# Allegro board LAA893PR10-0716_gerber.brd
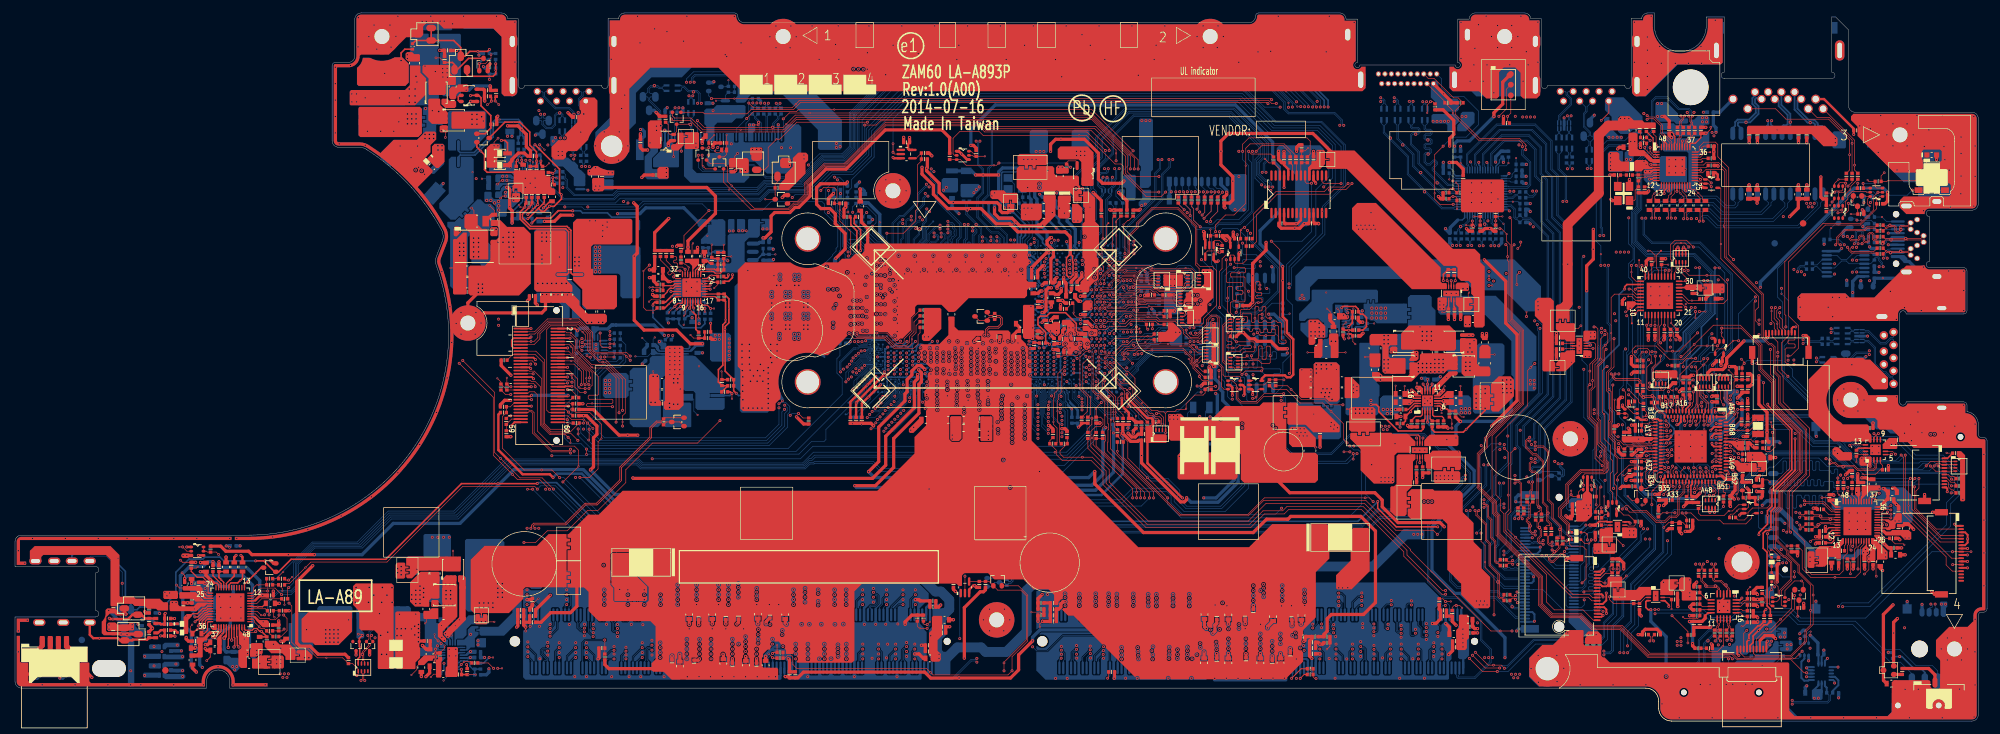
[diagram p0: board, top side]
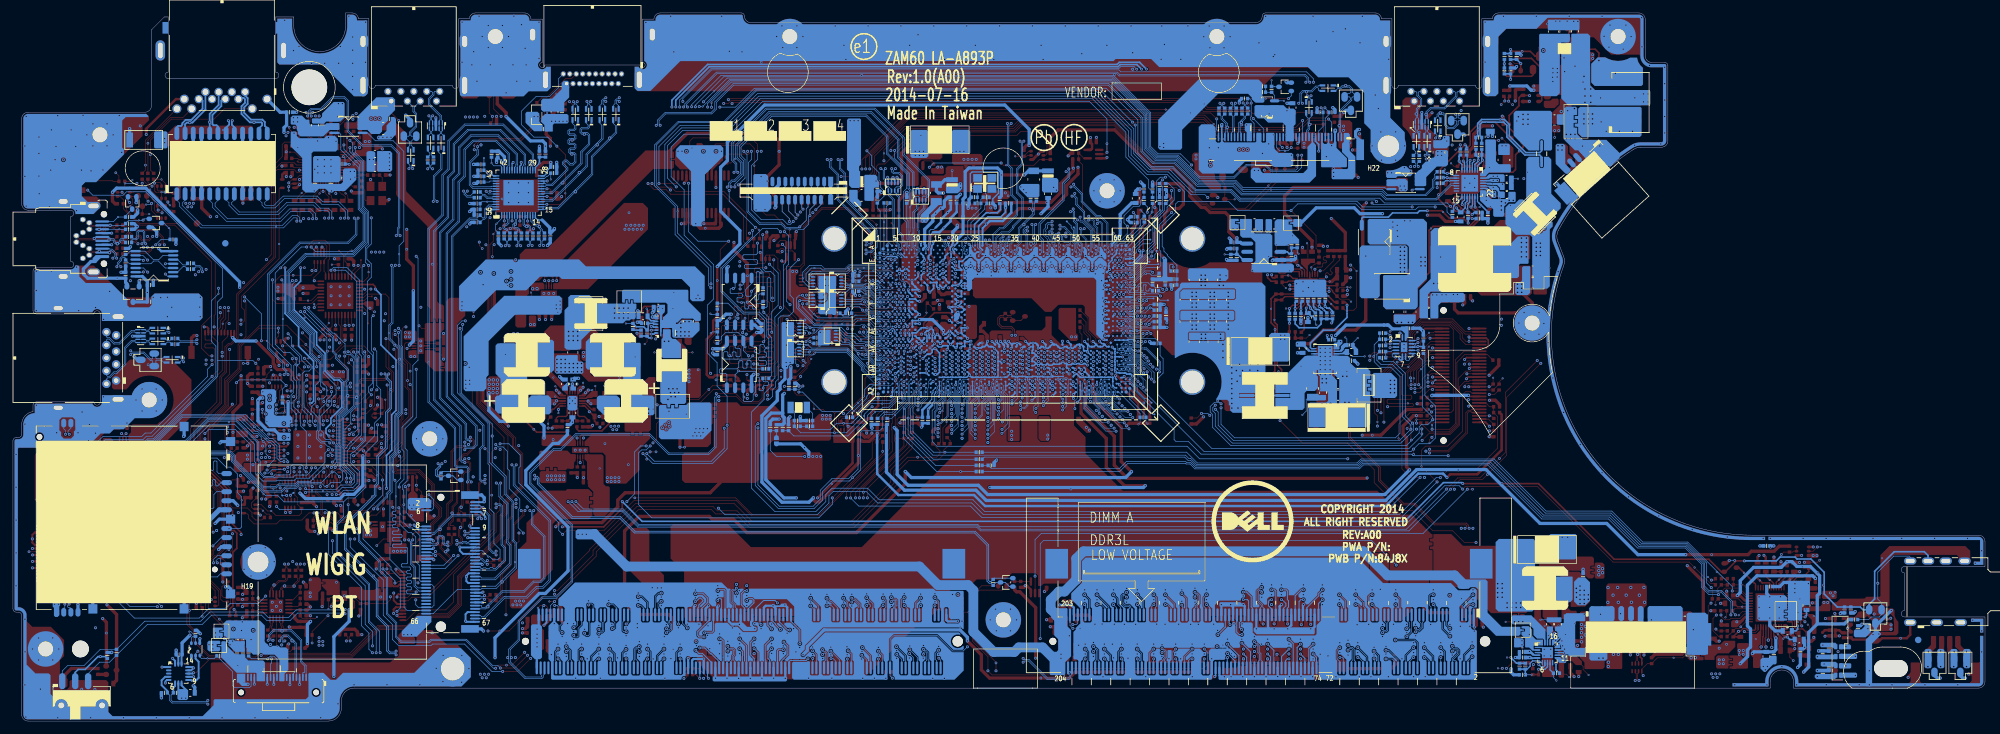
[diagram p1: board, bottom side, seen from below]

Outline 304.75 x 109.5 mm; copper layers: TOP, VCC, IN1, IN2, GND, BOTTOM. Coordinates in mm from the lower left corner of the outline.
Outline path: 0,27.75 arc(0.29,28.46) 1,28.75 36,28.75 arc(61.42,42.01) 65.1,70.44 arc(64.98,71.14) 65.11,71.85 66.03,74.22 arc(66.16,75.07) 65.92,75.89 arc(60.9,82.9) 54.28,88.42 arc(53.76,88.65) 53.2,88.73 50,88.73 arc(49.29,89.03) 49,89.73 49,101.35 arc(49.15,101.7) 49.5,101.85 51.5,101.85 arc(52.21,102.14) 52.5,102.85 52.5,108.5 arc(52.79,109.21) 53.5,109.5 75.15,109.5 arc(75.83,109.24) 76.15,108.6 77.75,108.6 77.75,98.3 arc(78.25,97.8) 78.75,98.3 90.65,98.3 arc(91.15,97.8) 91.65,98.3 91.65,108.6 93.25,108.6 arc(93.57,109.24) 94.24,109.5 111.2,109.5 arc(111.55,109.35) 111.7,109 arc(111.99,108.29) 112.7,108 190.7,108 arc(191.41,108.29) 191.7,109 arc(191.85,109.35) 192.2,109.5 204.7,109.5 arc(205.39,109.22) 205.7,108.55 207.45,108.55 207.45,101.85 arc(207.17,101.17) 207.85,101.45 222.55,101.45 arc(223.23,101.17) 222.95,101.85 222.95,108.55 224.7,108.55 arc(225.01,109.22) 225.7,109.5 233.25,109.5 arc(233.93,109.24) 234.25,108.6 235.85,108.6 235.85,98.3 arc(236.35,97.8) 236.85,98.3 248.75,98.3 arc(249.25,97.8) 249.75,98.3 249.75,108.6 251.35,108.6 arc(251.67,109.24) 252.34,109.5 253.35,109.5 253.35,107.5 arc(257.35,103.5) 261.35,107.5 261.35,108.88 264.15,108.88 264.15,100.35 arc(263.65,99.87) 264.1,99.35 arc(264.13,99.35) 264.15,99.35 280.75,99.35 arc(280.77,99.35) 280.8,99.35 arc(281.25,99.87) 280.75,100.35 280.75,108.88 281.35,108.88 283.35,106.88 283.35,95.15 arc(283.64,94.44) 284.35,94.15 302.4,94.15 arc(303.11,93.86) 303.4,93.15 303.4,80 arc(303.11,79.29) 302.4,79 295.85,79 arc(295.35,78.5) 295.85,78 295.85,71.1 arc(295.35,70.6) 295.85,70.1 301.15,70.1 arc(301.5,69.95) 301.65,69.6 301.65,63.45 arc(301.5,63.1) 301.15,62.95 292.25,62.95 arc(291.75,63.45) 291.25,62.95 291.25,49.35 arc(291.75,48.85) 292.25,49.35 301.15,49.35 arc(301.49,49.21) 301.65,48.88 301.65,47.85 arc(302.9,47.19) 303.4,45.87 303.4,44.34 arc(303.55,43.99) 303.9,43.84 304.25,43.84 arc(304.6,43.69) 304.75,43.34 304.75,17.35 arc(304.6,16.99) 304.25,16.85 303.9,16.85 arc(303.55,16.7) 303.4,16.35 303.4,1 arc(303.11,0.29) 302.4,0 256,0 arc(254.59,0.59) 254,2 254,3.1 arc(253.41,4.51) 252,5.1 33.2,5.1 33.2,6.1 arc(31.4,7.9) 29.6,6.1 29.6,5.1 1,5.1 arc(0.29,5.39) 0,6.1 0,16.1 12.45,16.1 arc(12.95,16.6) 12.45,17.1 12.45,22.9 arc(12.95,23.4) 12.45,23.9 0,23.9 0,27.75

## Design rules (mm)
net group CLK_PCIE_LAN: nets CLK_PCIE_LAN CLK_PCIE_LAN#
net group CLK_PCIE_MMI: nets CLK_PCIE_MMI CLK_PCIE_MMI#
net group CLK_PCIE_WIGIG: nets CLK_PCIE_WIGIG CLK_PCIE_WIGIG#
net group CLK_PCIE_WLAN: nets CLK_PCIE_WLAN CLK_PCIE_WLAN#
net group CPU_DPB_CTRLCLK: nets CPU_DPB_CTRLCLK CPU_DPB_CTRLDAT
net group CPU_DPC_CTRLCLK: nets CPU_DPC_CTRLCLK CPU_DPC_CTRLDAT
net group DDR_A_DQS0: nets DDR_A_DQS0 DDR_A_DQS#0
net group DDR_A_DQS1: nets DDR_A_DQS1 DDR_A_DQS#1
net group DDR_A_DQS2: nets DDR_A_DQS2 DDR_A_DQS#2
net group DDR_A_DQS3: nets DDR_A_DQS3 DDR_A_DQS#3
net group DDR_A_DQS4: nets DDR_A_DQS4 DDR_A_DQS#4
net group DDR_A_DQS5: nets DDR_A_DQS5 DDR_A_DQS#5
net group DDR_A_DQS6: nets DDR_A_DQS6 DDR_A_DQS#6
net group DDR_A_DQS7: nets DDR_A_DQS7 DDR_A_DQS#7
net group DDR_B_DQS0: nets DDR_B_DQS0 DDR_B_DQS#0
net group DDR_B_DQS1: nets DDR_B_DQS1 DDR_B_DQS#1
net group DDR_B_DQS2: nets DDR_B_DQS2 DDR_B_DQS#2
net group DDR_B_DQS3: nets DDR_B_DQS3 DDR_B_DQS#3
net group DDR_B_DQS4: nets DDR_B_DQS4 DDR_B_DQS#4
net group DDR_B_DQS5: nets DDR_B_DQS5 DDR_B_DQS#5
net group DDR_B_DQS6: nets DDR_B_DQS6 DDR_B_DQS#6
net group DDR_B_DQS7: nets DDR_B_DQS7 DDR_B_DQS#7
net group DIFFPAIR0: nets MCP_TESTLOW1 MCP_TESTLOW2
net group DIFFPAIR1: nets HDMI_CLK_AUX HDMI_DAT_AUX#
net group DIFFPAIR3: nets DMIC1 DMIC_CLK1
net group DIFFPAIR4: nets DMIC0 DMIC_CLK0
net group DIFFPAIR5: nets BC_CLK_ECE1117 BC_DAT_ECE1117
net group DIFFPAIR6: nets REM_DIODE4_N_R REM_DIODE4_P_R
net group EDP_CPU_AUX_C: nets EDP_CPU_AUX#_C EDP_CPU_AUX_C
net group M_CLK_DDR0: nets M_CLK_DDR0 M_CLK_DDR#0
net group M_CLK_DDR1: nets M_CLK_DDR1 M_CLK_DDR#1
net group M_CLK_DDR2: nets M_CLK_DDR2 M_CLK_DDR#2
net group M_CLK_DDR3: nets M_CLK_DDR3 M_CLK_DDR#3
net group MDP_AUX_C: nets MDP_AUX#_C MDP_AUX_C
net group PBAT_SMBCLK_C: nets PBAT_SMBCLK_C PBAT_SMBDAT_C
net group PS_USBP1_D: nets PS_USBP1_D+ PS_USBP1_D-
net group SATA_PRX_DTX_1: nets SATA_PRX_DTX_N1 SATA_PRX_DTX_P1
net group SATA_PRX_DTX_1_C: nets SATA_PRX_DTX_N1_C SATA_PRX_DTX_P1_C
net group SATA_PRX_DTX_1_RP: nets SATA_PRX_DTX_N1_RP SATA_PRX_DTX_P1_RP
net group SATA_PRX_DTX_1_RP_C: nets SATA_PRX_DTX_N1_RP_C SATA_PRX_DTX_P1_RP_C
net group SATA_PTX_DRX_1: nets SATA_PTX_DRX_N1 SATA_PTX_DRX_P1
net group SATA_PTX_DRX_1_C: nets SATA_PTX_DRX_N1_C SATA_PTX_DRX_P1_C
net group SATA_PTX_DRX_1_RP: nets SATA_PTX_DRX_N1_RP SATA_PTX_DRX_P1_RP
net group SATA_PTX_DRX_1_RP_C: nets SATA_PTX_DRX_N1_RP_C SATA_PTX_DRX_P1_RP_C
net group SENSE: nets VCCSENSE VSSSENSE
net group SINGLE-CLK: nets CLK_PCI_LPDEBUG CLK_PCI_MEC
net group SW_MDP_AUX: nets SW_MDP_AUX#_C SW_MDP_AUX_C
net group TMDS_CON_CLK: nets TMDS_CON_CLK TMDS_CON_CLK#
net group USB2.0: nets USBP4+ USBP4-
net group USB3RN1_D: nets USB3RN1_D- USB3RP1_D+
net group USB3RN2_D: nets USB3RN2_D- USB3RP2_D+
net group USB3RP4_D: nets USB3RN4_D- USB3RP4_D+
net group USB3T1: nets USB3TN1 USB3TP1
net group USB3T1_C: nets USB3TN1_C USB3TP1_C
net group USB3T2: nets USB3TN2 USB3TP2
net group USB3T2_C: nets USB3TN2_C USB3TP2_C
net group USB3T4: nets USB3TN4 USB3TP4
net group USB3T4_C: nets USB3TN4_C USB3TP4_C
net group USB3TN1_D: nets USB3TN1_D- USB3TP1_D+
net group USB3TN2_D: nets USB3TN2_D- USB3TP2_D+
net group USB3TP4_D: nets USB3TN4_D- USB3TP4_D+
net group USBP0: nets USBP0+ USBP0-
net group USBP0_D: nets USBP0_D+ USBP0_D-
net group USBP1: nets USBP1+ USBP1-
net group USBP1_R_D: nets USBP1_R_D+ USBP1_R_D-
net group USBP2: nets USBP2+ USBP2-
net group USBP3: nets USBP3+ USBP3-
net group USBP3_D: nets USBP3_D+ USBP3_D-
net group USBP4_D: nets USBP4_D+ USBP4_D-
net group USBP5: nets USBP5+ USBP5-
net group USBP5_D: nets USBP5_D+ USBP5_D-
net group WIGIG_AUX: nets WIGIG_AUX WIGIG_AUX#
net group WIGIG_AUX_C: nets WIGIG_AUX#_C WIGIG_AUX_C
net group 10: nets +PCH_ASATA3PLL +PCH_AUSB3PLL AUD_HP_OUT_L AUD_HP_OUT_L1 AUD_HP_OUT_R AUD_HP_OUT_R1 AUD_OUT_L AUD_OUT_R CFG_RCOMP PCH_PCIE_RCOMP PROC_OPI_RCOMP SATA_COMP SM_RCOMP0 SM_RCOMP1 SM_RCOMP2 TDI_IREF
net group 12/15: nets H_CATERR# H_PROCHOT# H_PROCHOT#_R H_THERMTRIP# H_THERMTRIP#_R PCH_PLTRST# PCH_PLTRST#_EC PLTRST_LAN# PLTRST_MMI# THERMATRIP2# THERMATRIP3# XDP_OBS0_R XDP_OBS1_R XDP_OBS2_R XDP_OBS3_R XDP_OBS4_R XDP_OBS5_R XDP_OBS6_R XDP_OBS7_R XDP_RST#_R
net group 15: nets CHARGER_SMBCLK CLK_TP_SIO DDR_XDP_WAN_SMBCLK GPU_SMBCLK MEM_SMBCLK PBAT_SMBCLK PCH_SPI_CLK SML0_SMBCLK SML1_SMBCLK SPI_CLK32 SPI_CLK64 SPI_PCH_CLK SYS_PWROK USH_SMBCLK
net group 20: nets +SM_VREF_CA +SM_VREF_DQ0 +SM_VREF_DQ1 DDR3_DRAMRST# EDP_COMP
net group ASYNC: nets H_CPUPWRGD PCH_JTAG_TCK PCH_JTAG_TDI PCH_JTAG_TDO PCH_JTAG_TMS
net group BUS_CL: nets PCH_CL_CLK1 PCH_CL_DATA1 PCH_CL_RST1#
net group BUS_RTC: nets PCH_RTCRST# PCH_RTCX1 PCH_RTCX1_R PCH_RTCX2 SRTCRST#
net group DDI1: nets CPU_DPB_AUX CPU_DPB_AUX# DDI1_LANE_N0 DDI1_LANE_N1 DDI1_LANE_N2 DDI1_LANE_N3 DDI1_LANE_P0 DDI1_LANE_P1 DDI1_LANE_P2 DDI1_LANE_P3 MDP_LANE_N0_C MDP_LANE_N1_C MDP_LANE_N2_C MDP_LANE_N3_C MDP_LANE_P0_C MDP_LANE_P1_C MDP_LANE_P2_C MDP_LANE_P3_C
net group DDI2: nets CPU_DPC_AUX CPU_DPC_AUX# CPU_DPC_AUX#_C CPU_DPC_AUX_C DDI2_LANE_N0 DDI2_LANE_N0_C DDI2_LANE_N1 DDI2_LANE_N1_C DDI2_LANE_N2 DDI2_LANE_N2_C DDI2_LANE_N3 DDI2_LANE_N3_C DDI2_LANE_P0 DDI2_LANE_P0_C DDI2_LANE_P1 DDI2_LANE_P1_C DDI2_LANE_P2 DDI2_LANE_P2_C DDI2_LANE_P3 DDI2_LANE_P3_C
net group DDRA_CMD: nets DDR_A_BS0 DDR_A_BS1 DDR_A_BS2 DDR_A_CAS# DDR_A_MA0 DDR_A_MA1 DDR_A_MA2 DDR_A_MA3 DDR_A_MA4 DDR_A_MA5 DDR_A_MA6 DDR_A_MA7 DDR_A_MA8 DDR_A_MA9 DDR_A_MA10 DDR_A_MA11 DDR_A_MA12 DDR_A_MA13 DDR_A_MA14 DDR_A_MA15 DDR_A_RAS# DDR_A_WE#
net group DDRA_CTL: nets DDR_CKE0_DIMMA DDR_CKE1_DIMMA DDR_CS0_DIMMA# DDR_CS1_DIMMA# M_ODT0 M_ODT1
net group DDRB_CMD: nets DDR_B_BS0 DDR_B_BS1 DDR_B_BS2 DDR_B_CAS# DDR_B_MA0 DDR_B_MA1 DDR_B_MA2 DDR_B_MA3 DDR_B_MA4 DDR_B_MA5 DDR_B_MA6 DDR_B_MA7 DDR_B_MA8 DDR_B_MA9 DDR_B_MA10 DDR_B_MA11 DDR_B_MA12 DDR_B_MA13 DDR_B_MA14 DDR_B_MA15 DDR_B_RAS# DDR_B_WE#
net group DDRB_CTL: nets DDR_CKE2_DIMMB DDR_CKE3_DIMMB DDR_CS2_DIMMB# DDR_CS3_DIMMB# M_ODT2 M_ODT3
net group EDP: nets EDP_CPU_AUX EDP_CPU_AUX# EDP_CPU_LANE_N0 EDP_CPU_LANE_N0_C EDP_CPU_LANE_N1 EDP_CPU_LANE_N1_C EDP_CPU_LANE_P0 EDP_CPU_LANE_P0_C EDP_CPU_LANE_P1 EDP_CPU_LANE_P1_C
net group HDA: nets ME_FWP PCH_AZ_BITCLK PCH_AZ_CODEC_BITCLK PCH_AZ_CODEC_RST# PCH_AZ_CODEC_SDIN0 PCH_AZ_CODEC_SDOUT PCH_AZ_CODEC_SYNC PCH_AZ_RST# PCH_AZ_SDIN0_R PCH_AZ_SDOUT PCH_AZ_SYNC
net group HDMI: nets HDMI_LANE_N0 HDMI_LANE_N1 HDMI_LANE_N2 HDMI_LANE_N3 HDMI_LANE_P0 HDMI_LANE_P1 HDMI_LANE_P2 HDMI_LANE_P3 TMDS_CON_N0 TMDS_CON_N1 TMDS_CON_N2 TMDS_CON_P0 TMDS_CON_P1 TMDS_CON_P2
net group LAN: nets LAN_TX0+ LAN_TX0+L LAN_TX0- LAN_TX0-L LAN_TX1+ LAN_TX1+L LAN_TX1- LAN_TX1-L LAN_TX2+ LAN_TX2+L LAN_TX2- LAN_TX2-L LAN_TX3+ LAN_TX3+L LAN_TX3- LAN_TX3-L
net group MEM_SMB: nets MEM_SMBDATA
net group PCIE: nets PCIE_PRX_GLANTX_N3 PCIE_PRX_GLANTX_N3_C PCIE_PRX_GLANTX_P3 PCIE_PRX_GLANTX_P3_C PCIE_PRX_MMITX_N1 PCIE_PRX_MMITX_N1_C PCIE_PRX_MMITX_P1 PCIE_PRX_MMITX_P1_C PCIE_PRX_WIGIGTX_N5 PCIE_PRX_WIGIGTX_P5 PCIE_PRX_WLANTX_N4 PCIE_PRX_WLANTX_P4 PCIE_PTX_GLANRX_N3 PCIE_PTX_GLANRX_N3_C PCIE_PTX_GLANRX_P3 PCIE_PTX_GLANRX_P3_C PCIE_PTX_MMIRX_N1 PCIE_PTX_MMIRX_N1_C PCIE_PTX_MMIRX_P1 PCIE_PTX_MMIRX_P1_C PCIE_PTX_WIGIGRX_N5 PCIE_PTX_WIGIGRX_N5_C PCIE_PTX_WIGIGRX_P5 PCIE_PTX_WIGIGRX_P5_C PCIE_PTX_WLANRX_N4 PCIE_PTX_WLANRX_N4_C PCIE_PTX_WLANRX_P4 PCIE_PTX_WLANRX_P4_C
net group R_DQA0: nets DDR_A_D0 DDR_A_D1 DDR_A_D2 DDR_A_D3 DDR_A_D4 DDR_A_D5 DDR_A_D6 DDR_A_D7
net group R_DQA1: nets DDR_A_D8 DDR_A_D9 DDR_A_D10 DDR_A_D11 DDR_A_D12 DDR_A_D13 DDR_A_D14 DDR_A_D15
net group R_DQA2: nets DDR_A_D16 DDR_A_D17 DDR_A_D18 DDR_A_D19 DDR_A_D20 DDR_A_D21 DDR_A_D22 DDR_A_D23
net group R_DQA3: nets DDR_A_D24 DDR_A_D25 DDR_A_D26 DDR_A_D27 DDR_A_D28 DDR_A_D29 DDR_A_D30 DDR_A_D31
net group R_DQA4: nets DDR_A_D32 DDR_A_D33 DDR_A_D34 DDR_A_D35 DDR_A_D36 DDR_A_D37 DDR_A_D38 DDR_A_D39
net group R_DQA5: nets DDR_A_D40 DDR_A_D41 DDR_A_D42 DDR_A_D43 DDR_A_D44 DDR_A_D45 DDR_A_D46 DDR_A_D47
net group R_DQA6: nets DDR_A_D48 DDR_A_D49 DDR_A_D50 DDR_A_D51 DDR_A_D52 DDR_A_D53 DDR_A_D54 DDR_A_D55
net group R_DQA7: nets DDR_A_D56 DDR_A_D57 DDR_A_D58 DDR_A_D59 DDR_A_D60 DDR_A_D61 DDR_A_D62 DDR_A_D63
net group R_DQB0: nets DDR_B_D0 DDR_B_D1 DDR_B_D2 DDR_B_D3 DDR_B_D4 DDR_B_D5 DDR_B_D6 DDR_B_D7
net group R_DQB1: nets DDR_B_D8 DDR_B_D9 DDR_B_D10 DDR_B_D11 DDR_B_D12 DDR_B_D13 DDR_B_D14 DDR_B_D15
net group R_DQB2: nets DDR_B_D16 DDR_B_D17 DDR_B_D18 DDR_B_D19 DDR_B_D20 DDR_B_D21 DDR_B_D22 DDR_B_D23
net group R_DQB3: nets DDR_B_D24 DDR_B_D25 DDR_B_D26 DDR_B_D27 DDR_B_D28 DDR_B_D29 DDR_B_D30 DDR_B_D31
net group R_DQB4: nets DDR_B_D32 DDR_B_D33 DDR_B_D34 DDR_B_D35 DDR_B_D36 DDR_B_D37 DDR_B_D38 DDR_B_D39
net group R_DQB5: nets DDR_B_D40 DDR_B_D41 DDR_B_D42 DDR_B_D43 DDR_B_D44 DDR_B_D45 DDR_B_D46 DDR_B_D47
net group R_DQB6: nets DDR_B_D48 DDR_B_D49 DDR_B_D50 DDR_B_D51 DDR_B_D52 DDR_B_D53 DDR_B_D54 DDR_B_D55
net group R_DQB7: nets DDR_B_D56 DDR_B_D57 DDR_B_D58 DDR_B_D59 DDR_B_D60 DDR_B_D61 DDR_B_D62 DDR_B_D63
net group RJ45: nets NB_LAN_TX0+ NB_LAN_TX0- NB_LAN_TX1+ NB_LAN_TX1- NB_LAN_TX2+ NB_LAN_TX2- NB_LAN_TX3+ NB_LAN_TX3-
net group SD-CARD: nets SD/MMCCD# SD/MMCCLK SD/MMCCLK_R SD/MMCCMD SD/MMCDAT0 SD/MMCDAT1 SD/MMCDAT2 SD/MMCDAT2_R SD/MMCDAT3 SD/MMCDAT3_R SD_REXT SD_UHS2_D0N SD_UHS2_D0P SD_UHS2_D1N SD_UHS2_D1P SDWP
net group SMBUS: nets CHARGER_SMBDAT DAT_TP_SIO DDR_XDP_WAN_SMBDAT GPU_SMBDAT PBAT_SMBDAT USH_SMBDAT
net group SML0_SMB: nets SML0_SMBDATA
net group SML1_SMB: nets SML1_SMBDATA
net group SPI: nets PCH_SPI_CS0# PCH_SPI_CS1# PCH_SPI_DIN PCH_SPI_DO PCH_SPI_DO2 PCH_SPI_DO3 SPI_DIN32 SPI_DIN64 SPI_DO32 SPI_DO64 SPI_PCH_CS0# SPI_PCH_CS0#_R SPI_PCH_CS1# SPI_PCH_CS1#_R SPI_PCH_DIN SPI_PCH_DO SPI_PCH_DO2 SPI_PCH_DO2_32 SPI_PCH_DO2_64 SPI_PCH_DO3 SPI_PCH_DO3_32 SPI_PCH_DO3_64
net group SPK: nets INT_SPK_L+ INT_SPK_L- INT_SPK_R+ INT_SPK_R- INT_SPKR_L+ INT_SPKR_L- INT_SPKR_R+ INT_SPKR_R-
net group SVID: nets VIDALERT_N VIDSCLK VIDSOUT
net group THERMAL: nets REM_DIODE1_N REM_DIODE1_P REM_DIODE2_N REM_DIODE2_P REM_DIODE4_N REM_DIODE4_P
net group USB3.0-20: nets USB3RN1 USB3RN2 USB3RN4 USB3RP1 USB3RP2 USB3RP4
net group WIGIG: nets WIGIG_LANE_N0 WIGIG_LANE_N0_C WIGIG_LANE_N1 WIGIG_LANE_N1_C WIGIG_LANE_N2 WIGIG_LANE_N2_C WIGIG_LANE_N3 WIGIG_LANE_N3_C WIGIG_LANE_P0 WIGIG_LANE_P0_C WIGIG_LANE_P1 WIGIG_LANE_P1_C WIGIG_LANE_P2 WIGIG_LANE_P2_C WIGIG_LANE_P3 WIGIG_LANE_P3_C
nets with their own width: min track width 0.254; nets AC_DIS AUD_HP_NB_SENSE AUD_SENSE_A BAT1_LED# BAT2_LED# BATT_WHITE# BATT_YELLOW# CLK_BIASREF N20923205 PS_ID
nets with their own width: min track width 0.381; nets +PCH_RTC_VCCSUS3_3 +PCH_VCCDSW3_3 N20249232 N20249233 PCH_OPI_COMP
nets with their own width: min track width 0.508; nets +0.9V_LAN +1.2V_LDO +1.05V_M +1.05V_MODPHY +1.05V_MODPHY_PCH +1.05V_MP +1.05V_RUN +1.5V_RUN +1.5V_RUN_AUDIO +1.05V_VCCST +1.35V_MEM +1.35V_MEN_P +3.3V_ALW +3.3V_ALW2 +3.3V_ALW_PCH +3.3V_ALW_UE2 +3.3V_ALW_UE3 +3.3V_ALWP +3.3V_CAM +3.3V_HDD +3.3V_M +3.3V_MMI +3.3V_RTC_LDO +3.3V_RUN +3.3V_RUN_AUDIO +3.3V_RUN_UZ9 +3.3V_SPI +3.3V_TP +5V_ALW +5V_ALW2 +5V_ALWP +5V_RUN_AUDIO +5V_RUN_UZ9 +AUX_LDO +BL_PWR_SRC +COINCELL +DC_IN +DC_IN_SS +DCIN +DCIN_JACK +DCPRRTC +DIMM1_VREF_DQ +DIMM2_VREF_DQ +GND_CHASSIS +MIC1_VREF_OUT +PBATT +PCH_VCC1P05 +PCH_VCCACLKPLL +PCH_VCCDSW +PCH_VCCDSW_R +RTC_CELL +RTC_CELL_VBAT +SD_IO_LDO +SM_VREF_CA_DIMM +USB_RIGHT_PWR +V_DDR_REF +VCC_CORE +VCCIO_OUT +VCCIOA_OUT +VDDA_AVDD1 +VDDA_PVDD +VDISPLAY_VCC +VHDMI_VCC +VLDOIN_1.35V +VR_CAP +VREFOUT +Z4012 BQ24770_REGN GND GNDA N33048 N33050 N18292467 N18325201 N18325205 N18325209 N18325213 Z2805 Z2806 Z2807 Z2808
nets with their own width: min track width 0.762; nets +1.8V_RUN_CARD +3.3V_RUN_CARD
nets with their own width: min track width 1.016; nets RING2_R SLEEVE
nets with their own width: min track width 1.27; nets RING2
nets with their own width: min track width 1.524; nets +0.675V_DDR_VTT +0.675V_P +3.3V_LAN +5V_HDD +LCDVDD
nets with their own width: min track width 2.032; nets +3.3V_WLAN +5V_RUN +USB_LEFT_PWR
nets with their own width: min track width 2.54; nets +5V_USB_CHG_PWR
nets with their own width: min track width 2.794; nets +1.05V_RUN_UZ8

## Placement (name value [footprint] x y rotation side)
CA1  680P_0402_50V7K  [C_0402]  20.74 17.64 270 top
CA2  220P_0402_50V7K  [C_0402]  20.72 15.87 270 top
CA3  220P_0402_50V7K  [C_0402]  20.71 12.88 90 top
CA4  680P_0402_50V7K  [C_0402]  19.64 13.83 90 bottom
CA5  100P_0402_50V8J  [C_0402]  102.3 94.14 0 bottom
CA6  100P_0402_50V8J  [C_0402]  101.37 94.14 180 bottom
CA8  0.1U_0402_25V6  [C_0402]  28.37 20.54 90 top
CA9  10U_0603_6.3V6M  [C_0603]  27.29 20.56 90 top
CA10  4.7U_0603_6.3V6K  [C_0603]  41.89 11.35 90 top
CA11  0.1U_0402_25V6  [C_0402]  38.88 14.85 0 top
CA12  680P_0402_50V7K  [C_0402]  15.2 18.02 270 top
CA13  680P_0402_50V7K  [C_0402]  15.2 14.44 270 top
CA16  4.7U_0603_6.3V6K  [C_0603]  31.57 10.92 180 top
CA17  0.1U_0402_25V6  [C_0402]  28.33 12.36 180 top
CA18  4.7U_0603_6.3V6K  [C_0603]  28.57 11.28 180 top
CA19  1000P_0402_50V7K  [C_0402]  25.07 9.94 90 bottom
CA22  1000P_0402_50V7K  [C_0402]  25.07 6.89 90 bottom
CA23  1000P_0402_50V7K  [C_0402]  24.11 8.82 270 bottom
CA24  1000P_0402_50V7K  [C_0402]  24.11 11.74 270 bottom
CA25  10U_0603_6.3V6M  [C_0603]  27.58 17.17 90 bottom
CA26  1U_0603_10V4Z  [C_0603]  29.51 23.1 90 top
CA27  0.1U_0402_25V6  [C_0402]  39.81 22.02 180 top
CA28  0.1U_0402_25V6  [C_0402]  39.81 21.06 180 top
CA29  1U_0603_10V6K  [C_0603]  27.42 13.52 0 top
CA30  22P_0402_50V8J  [C_0402]  230.93 92.47 180 top
CA31  1U_0603_10V6K  [C_0603]  37.81 13.02 270 top
CA33  15P_0402_50V8J  [C_0402]  40.84 17.06 0 top
CA35  2.2U_0402_6.3V6M  [C_0402]  27.23 24.56 270 top
CA41  0.1U_0402_25V6  [C_0402]  20.74 17.64 270 bottom
CA43  4.7U_0603_6.3V6K  [C_0603]  35.15 23.12 90 top
CA44  4.7U_0603_6.3V6K  [C_0603]  33.88 23.12 90 top
CA45  0.1U_0402_25V6  [C_0402]  35.87 11.61 0 top
CA46  10U_0603_6.3V6M  [C_0603]  33.78 10.71 270 bottom
CA47  0.1U_0402_25V6  [C_0402]  32.64 10.72 270 bottom
CA48  10U_0603_6.3V6M  [C_0603]  35.24 10.45 0 top
CA49  1U_0603_10V6K  [C_0603]  31.24 13.94 180 bottom
CA50  0.1U_0402_25V6  [C_0402]  39 19.4 0 top
CA51  4.7U_0603_6.3V6K  [C_0603]  32.61 23.12 90 top
CA52  4.7U_0603_6.3V6K  [C_0603]  29.4 12.61 180 bottom
CA53  4.7U_0603_6.3V6K  [C_0603]  38.76 18.21 0 top
CA54  22P_0402_50V8J  [C_0402]  40.75 13.94 90 top
CC1  15P_0402_50V8J  [C_0402]  182.09 46.47 180 bottom
CC2  12P_0402_50V8J  [C_0402]  183.08 46.47 0 bottom
CC3  1U_0402_6.3V6K  [C_0402]  184.9 45.82 270 bottom
CC4  1U_0402_6.3V6K  [C_0402]  187.72 45.83 270 bottom
CC5  27P_0402_50V8J  [C_0402]  154.05 39.54 180 bottom
CC6  0.1U_0402_25V6  [C_0402]  189.04 60.5 90 bottom
CC7  0.1U_0402_25V6  [C_0402]  195.89 57.57 270 bottom
CC8  15P_0402_50V8J  [C_0402]  153.32 80.06 0 bottom
CC9  33P_0402_50V8J  [C_0402]  195.89 61.1 270 bottom
CC10  33P_0402_50V8J  [C_0402]  195.89 61.95 90 bottom
CC11  15P_0402_50V8J  [C_0402]  156.65 81.01 180 bottom
CC12  12P_0402_50V8J  [C_0402]  160.4 44.75 270 top
CC13  12P_0402_50V8J  [C_0402]  162.56 44.75 270 top
CC17  0.1U_0402_25V6  [C_0402]  89.34 60.75 180 bottom
CC20  22P_0402_50V8J  [C_0402]  124.88 67.44 0 bottom
CC21  0.1U_0402_25V6  [C_0402]  86.2 49.07 0 top
CC22  0.1U_0402_25V6  [C_0402]  75.93 48.6 180 top
CC23  22U_0603_6.3V6M  [C_0603]  144.7 63.61 270 top
CC24  100P_0402_50V8J  [C_0402]  140.07 87.83 0 top
CC25  2.2U_0402_6.3V6M  [C_0402]  148.56 46.78 0 top
CC26  2.2U_0402_6.3V6M  [C_0402]  151.29 59.42 0 top
CC27  2.2U_0402_6.3V6M  [C_0402]  148.89 58.26 90 top
CC28  2.2U_0402_6.3V6M  [C_0402]  155.13 59.39 180 top
CC29  10U_0603_6.3V6M  [C_0603]  148.32 45.7 0 top
CC30  10U_0603_6.3V6M  [C_0603]  148.32 44.43 0 top
CC31  10U_0603_6.3V6M  [C_0603]  147.3 46.59 180 top
CC32  10U_0603_6.3V6M  [C_0603]  147.3 45.32 180 top
CC33  10U_0603_6.3V6M  [C_0603]  141.48 46.58 180 top
CC34  10U_0603_6.3V6M  [C_0603]  143.51 46.58 0 top
CC35  0.1U_0402_25V6  [C_0402]  138.24 89.47 180 top
CC36  22U_0603_6.3V6M  [C_0603]  156.08 61.44 180 top
CC37  1U_0402_6.3V6K  [C_0402]  156.12 60.28 180 top
CC39  330U_D3_2.5VY_R6M  [C_D2]  164.72 89.88 180 bottom
CC40  1U_0402_6.3V6K  [C_0402]  165.31 66.62 270 top
CC41  330U_D3_2.5VY_R6M  [C_D3]  187.05 45.09 270 top
CC42  330U_D3_2.5VY_R6M  [C_D3]  182.23 45.09 270 top
CC43  1U_0402_6.3V6K  [C_0402]  165.62 78.08 180 top
CC44  1U_0402_6.3V6K  [C_0402]  164.14 66.95 90 top
CC47  22U_0603_6.3V6M  [C_0603]  159.69 79.48 180 top
CC49  0.1U_0402_10V7K  [C_0402]  162.37 59.1 180 top
CC50  1U_0402_6.3V6K  [C_0402]  163 56.97 180 top
CC51  22U_0603_6.3V6M  [C_0603]  159.69 78.28 180 top
CC52  0.1U_0402_10V7K  [C_0402]  165.38 60.83 90 top
CC55  22U_0603_6.3V6M  [C_0603]  162.29 79.48 0 top
CC56  22U_0603_6.3V6M  [C_0603]  162.29 78.21 0 top
CC57  0.1U_0402_10V7K  [C_0402]  159.38 61.05 90 top
CC58  1U_0402_6.3V6K  [C_0402]  157.99 59.4 90 top
CC59  1U_0402_6.3V6K  [C_0402]  162.32 67.79 180 top
CC60  10U_0603_6.3V6M  [C_0603]  162.43 65.76 0 top
CC61  1U_0402_6.3V6K  [C_0402]  162.15 61.57 270 top
CC63  22U_0603_6.3V6M  [C_0603]  160.87 61.05 90 top
CC64  22U_0603_6.3V6M  [C_0603]  160.14 66.15 270 top
CC65  1U_0402_6.3V6K  [C_0402]  157.48 58.53 270 top
CC66  0.1U_0402_10V7K  [C_0402]  161.21 65.96 270 top
CC67  100U_1206_6.3V6M  [C_1206]  172.3 81.29 0 bottom
CC68  1U_0402_6.3V6K  [C_0402]  171.18 82.86 270 bottom
CC69  1U_0402_6.3V6K  [C_0402]  165.39 63.77 270 top
CC70  1U_0402_6.3V6K  [C_0402]  158.04 64.89 270 top
CC71  1U_0402_6.3V6K  [C_0402]  163.26 67.87 270 top
CC72  1U_0402_6.3V6K  [C_0402]  160.58 58.26 90 top
CC73  1U_0402_6.3V6K  [C_0402]  173.21 46.21 270 top
CC77  100U_1206_6.3V6M  [C_1206]  162.04 82.98 270 bottom
CC78  1U_0402_6.3V6K  [C_0402]  160.28 67.79 180 top
CC79  22U_0603_6.3V6M  [C_0603]  130.62 80.33 270 top
CC80  1U_0402_6.3V6K  [C_0402]  164.21 59.09 180 top
CC81  100U_1206_6.3V6M  [C_1206]  147 85.08 270 bottom
CC82  1U_0402_6.3V6K  [C_0402]  157.92 80.06 180 bottom
CC83  100P_0402_50V8J  [C_0402]  131.02 77.09 0 bottom
CC84  22U_0603_6.3V6M  [C_0603]  157.36 66.14 90 top
CC85  22U_0603_6.3V6M  [C_0603]  144.79 82.27 270 bottom
CC95  680P_0402_50V7K  [C_0402]  80.41 65.73 180 top
CC96  680P_0402_50V7K  [C_0402]  96.64 89.93 270 top
CC97  0.47U_0402_10V6K  [C_0402]  165.35 58.93 90 top
CC100  1U_0402_6.3V6K  [C_0402]  162.52 64.63 0 top
CD1  0.1U_0402_25V6  [C_0402]  78.61 15.29 180 top
CD2  1U_0402_6.3V6K  [C_0402]  116.63 16.85 270 top
CD3  1U_0402_6.3V6K  [C_0402]  111.81 16.69 270 top
CD4  1U_0402_6.3V6K  [C_0402]  109.84 16.63 270 top
CD5  2.2U_0402_6.3V6M  [C_0402]  78.61 16.24 180 top
CD6  0.1U_0402_25V6  [C_0402]  91.15 11.28 180 top
CD7  1U_0402_6.3V6K  [C_0402]  105.65 16.57 270 top
CD8  1U_0402_6.3V6K  [C_0402]  114.6 8.03 90 top
CD9  1U_0402_6.3V6K  [C_0402]  110.85 8.03 90 top
CD10  1U_0402_6.3V6K  [C_0402]  104.94 8.5 90 top
CD11  1U_0402_6.3V6K  [C_0402]  101.52 8.54 90 top
CD12  10U_0603_6.3V6M  [C_0603]  119.02 17.19 270 top
CD13  10U_0603_6.3V6M  [C_0603]  114.79 17.25 270 top
CD14  10U_0603_6.3V6M  [C_0603]  107.74 17.19 270 top
CD15  10U_0603_6.3V6M  [C_0603]  104.19 17.19 270 top
CD16  10U_0603_6.3V6M  [C_0603]  116 7.92 90 top
CD17  10U_0603_6.3V6M  [C_0603]  112.95 7.92 90 top
CD18  10U_0603_6.3V6M  [C_0603]  109.46 8.17 90 top
CD19  10U_0603_6.3V6M  [C_0603]  102.74 7.8 90 top
CD20  330U_D2_2V_Y  [C_D2]  99.96 24.55 180 top
CD21  0.022U_0402_16V7K  [C_0402]  80.45 17.19 180 top
CD22  0.1U_0402_25V6  [C_0402]  120.57 6.7 90 top
CD23  2.2U_0402_6.3V6M  [C_0402]  119.68 6.7 90 top
CD24  0.1U_0402_25V6  [C_0402]  141.6 10.78 180 top
CD25  0.1U_0402_25V6  [C_0402]  141.6 11.73 180 top
CD26  0.1U_0402_25V6  [C_0402]  142.91 13.63 0 top
CD27  0.1U_0402_25V6  [C_0402]  142.91 14.59 0 top
CD28  10U_0603_6.3V6M  [C_0603]  142.1 9.7 180 top
CD29  10U_0603_6.3V6M  [C_0603]  142.92 15.67 0 top
CD30  0.1U_0402_25V6  [C_0402]  145.02 21.58 270 top
CD31  2.2U_0402_6.3V6M  [C_0402]  142.3 18.59 180 top
CD32  0.1U_0402_25V6  [C_0402]  142.3 17.63 180 top
CD33  2.2U_0402_6.3V6M  [C_0402]  159.99 15.41 0 top
CD34  0.1U_0402_25V6  [C_0402]  159.99 16.36 0 top
CD35  0.1U_0402_25V6  [C_0402]  169.01 7.6 0 top
CD36  0.022U_0402_16V7K  [C_0402]  202.28 13.06 0 top
CD37  1U_0402_6.3V6K  [C_0402]  197.28 16.57 270 top
CD38  1U_0402_6.3V6K  [C_0402]  190.1 16.69 270 top
CD39  1U_0402_6.3V6K  [C_0402]  185.72 16.63 270 top
CD40  1U_0402_6.3V6K  [C_0402]  191.37 16.35 90 top
CD41  1U_0402_6.3V6K  [C_0402]  197.09 9.62 90 top
CD42  1U_0402_6.3V6K  [C_0402]  194.29 8.48 90 top
CD43  1U_0402_6.3V6K  [C_0402]  190.23 8.86 90 top
CD44  1U_0402_6.3V6K  [C_0402]  185.72 8.8 90 top
CD45  10U_0603_6.3V6M  [C_0603]  198.8 17.06 270 top
CD46  10U_0603_6.3V6M  [C_0603]  194.42 16.87 270 top
CD47  10U_0603_6.3V6M  [C_0603]  187.5 17.13 270 top
CD48  10U_0603_6.3V6M  [C_0603]  183.82 17.19 270 top
CD49  10U_0603_6.3V6M  [C_0603]  195.56 8.3 90 top
CD50  10U_0603_6.3V6M  [C_0603]  192.45 8.3 90 top
CD51  10U_0603_6.3V6M  [C_0603]  187.5 8.3 90 top
CD52  10U_0603_6.3V6M  [C_0603]  183.75 8.3 90 top
CD53  330U_D2_2V_Y  [C_D2]  201.57 28.4 0 top
CD54  0.022U_0402_16V7K  [C_0402]  158.09 17.32 0 top
CD55  0.1U_0402_25V6  [C_0402]  200.06 11.28 0 top
CD56  2.2U_0402_6.3V6M  [C_0402]  200.06 10.4 0 top
CD57  0.1U_0402_25V6  [C_0402]  223.07 11.41 180 top
CD58  0.1U_0402_25V6  [C_0402]  223.07 12.36 180 top
CD59  0.1U_0402_25V6  [C_0402]  224.38 13.63 0 top
CD60  0.1U_0402_25V6  [C_0402]  224.38 14.59 0 top
CD61  10U_0603_6.3V6M  [C_0603]  223.06 13.44 180 top
CD62  10U_0603_6.3V6M  [C_0603]  223.83 15.68 0 top
CD63  2.2U_0402_6.3V6M  [C_0402]  221.21 17.12 180 top
CD64  0.1U_0402_25V6  [C_0402]  221.21 16.24 180 top
CE1  10U_0603_6.3V6M  [C_0603]  262.95 66.71 270 top
CE2  0.1U_0402_25V6  [C_0402]  259.2 67.04 270 top
CE3  0.1U_0402_25V6  [C_0402]  249.31 64.49 180 top
CE8  0.047U_0402_16V4Z  [C_0402]  251.6 53.97 180 top
CE10  1U_0402_6.3V6K  [C_0402]  266.89 54.6 180 top
CE11  0.1U_0402_25V6  [C_0402]  266.9 50.85 90 top
CE12  1U_0402_6.3V6K  [C_0402]  266 52.79 90 top
CE13  0.1U_0402_25V6  [C_0402]  257.79 50.45 90 top
CE14  1U_0402_6.3V6K  [C_0402]  249.5 43.74 90 top
CE15  1U_0402_6.3V6K  [C_0402]  266.86 42.15 0 top
CE16  0.1U_0402_25V6  [C_0402]  251.34 41.11 90 top
CE17  0.1U_0402_25V6  [C_0402]  263.04 49.35 90 top
CE18  0.1U_0402_25V6  [C_0402]  266.99 38.92 270 top
CE19  0.1U_0402_25V6  [C_0402]  259.19 34.73 270 top
CE20  0.1U_0402_25V6  [C_0402]  266.86 43.03 0 top
CE21  10U_0603_6.3V6M  [C_0603]  269.86 40.75 0 top
CE22  0.1U_0402_25V6  [C_0402]  254.05 35.05 270 top
CE23  0.1U_0402_25V6  [C_0402]  248.61 43.74 90 top
CE24  2200P_0402_50V7K  [C_0402]  255.94 50.15 0 top
CE25  0.1U_0402_25V6  [C_0402]  265.03 34.79 270 top
CE26  2200P_0402_50V7K  [C_0402]  254.1 50.15 0 top
CE27  2200P_0402_50V7K  [C_0402]  253.81 49.25 180 top
CE28  33P_0402_50V8J  [C_0402]  267.71 44.94 270 top
CE29  33P_0402_50V8J  [C_0402]  267.76 45.82 90 top
CE30  1U_0402_6.3V6K  [C_0402]  258.34 31.03 0 top
CE31  4.7U_0603_6.3V6K  [C_0603]  256.42 52.26 90 top
CE32  10U_0603_6.3V6M  [C_0603]  64.93 86.19 225 top
CE34  4.7P_0402_50V8C  [C_0402]  249.5 38.76 270 top
CE35  100P_0402_50V8J  [C_0402]  151.4 63.03 270 top
CE36  0.1U_0402_25V6  [C_0402]  251.33 38.15 180 top
CE37  100P_0402_50V8J  [C_0402]  153.27 20.99 90 bottom
CE38  0.1U_0402_25V6  [C_0402]  251.33 45.77 180 top
CE39  100P_0402_50V8J  [C_0402]  100.21 46.72 270 top
CE40  4700P_0402_25V7K  [C_0402]  258.75 51.37 270 top
CE46  100P_0402_50V8J  [C_0402]  238.6 38.36 270 bottom
CI1  100U_1206_6.3V6M  [C_1206]  84.38 86.6 90 bottom
CI3  0.1U_0402_25V6  [C_0402]  87.18 93.39 180 top
CI4  0.1U_0402_10V7K  [C_0402]  87.42 87.47 270 bottom
CI5  0.1U_0402_10V7K  [C_0402]  88.31 87.47 270 bottom
CI6  10U_0603_6.3V6M  [C_0603]  89.65 83.48 90 top
CI7  0.1U_0402_25V6  [C_0402]  90.73 83.73 90 top
CI8  100U_1206_6.3V6M  [C_1206]  248.84 91.61 180 bottom
CI10  0.1U_0402_25V6  [C_0402]  247.01 93.14 180 bottom
CI11  10U_0603_6.3V6M  [C_0603]  258.05 91.43 90 bottom
CI12  0.1U_0402_25V6  [C_0402]  256.92 91.72 90 bottom
CI13  0.1U_0402_10V7K  [C_0402]  280.18 58.27 180 bottom
CI14  100U_1206_6.3V6M  [C_1206]  282.93 43.7 270 top
CI16  0.1U_0402_10V7K  [C_0402]  280.18 59.16 180 bottom
CI17  0.1U_0402_25V6K~D  [C_0402]  286.2 45.3 0 top
CI19  0.1U_0402_25V6K~D  [C_0402]  290.48 43.48 0 top
CI27  0.1U_0402_10V7K  [C_0402]  240.65 87.22 270 bottom
CI28  0.1U_0402_10V7K  [C_0402]  239.76 87.22 270 bottom
CL1  0.1U_0402_10V7K  [C_0402]  259.57 90.9 90 top
CL2  0.1U_0402_10V7K  [C_0402]  258.68 90.9 90 top
CL3  0.1U_0402_10V7K  [C_0402]  258.05 82.71 90 bottom
CL4  10U_0603_6.3V6M  [C_0603]  248.09 85.52 0 bottom
CL5  0.1U_0402_10V7K  [C_0402]  257.79 91.82 270 top
CL6  0.1U_0402_10V7K  [C_0402]  256.9 91.82 270 top
CL7  1U_0603_10V6K  [C_0603]  249.97 88.73 180 top
CL8  0.1U_0402_10V7K  [C_0402]  255.63 90.9 90 top
CL9  0.1U_0402_10V7K  [C_0402]  260.52 90.9 90 top
CL10  0.1U_0402_10V7K  [C_0402]  253.46 83.99 0 bottom
CL11  0.1U_0402_10V7K  [C_0402]  255.63 82.71 90 bottom
CL12  22U_0603_6.3V6M  [C_0603]  248.09 87.68 0 bottom
CL13  27P_0402_50V8J  [C_0402]  247.18 84.44 0 top
CL14  27P_0402_50V8J  [C_0402]  250.87 81.69 90 top
CL15  0.1U_0402_10V7K  [C_0402]  262.52 84.81 180 top
CL16  0.47U_0603_10V7K  [C_0603]  276.91 82.18 270 top
CL17  0.47U_0603_10V7K  [C_0603]  275.57 82.18 270 top
CL18  470P_0402_50V7K  [C_0402]  262.46 94.14 180 bottom
CL19  0.1U_0402_10V7K  [C_0402]  284.15 91.35 0 top
CL20  0.47U_0603_10V7K  [C_0603]  269.21 82.18 270 top
CL21  0.47U_0603_10V7K  [C_0603]  267.94 82.18 270 top
CL22  150P_1808_2.5KV8J  [C_1808]  286.72 89.85 180 bottom
CMOS1  SHORT PADS~D  [SHORTPADS-S]  186.76 43.34 90 bottom
CN1  10U_0603_6.3V6M  [C_0603]  278.05 4.36 180 bottom
CN2  0.1U_0402_25V6  [C_0402]  278.61 10.27 0 bottom
CN3  0.1U_0402_10V7K  [C_0402]  256.91 19.75 180 top
CN4  470P_0402_50V7K  [C_0402]  255.99 18.8 0 top
CN13  1000P_0402_50V7K  [C_0402]  269.22 10.07 90 bottom
CN14  0.1U_0402_25V6  [C_0402]  270.11 10.07 90 bottom
CN15  0.1U_0402_25V6  [C_0402]  270.11 13.01 270 bottom
CN16  0.1U_0402_25V6  [C_0402]  269.22 13.01 270 bottom
CN17  0.01U_0402_16V7K  [C_0402]  262.64 13.16 90 top
CN18  0.01U_0402_16V7K  [C_0402]  263.53 13.16 90 top
CN19  0.01U_0402_16V7K  [C_0402]  265.38 13.16 90 top
CN20  0.01U_0402_16V7K  [C_0402]  264.49 13.16 90 top
CN23  0.01U_0402_16V7K  [C_0402]  262.91 23.32 270 top
CN24  0.1U_0402_25V6  [C_0402]  260.33 15.4 270 top
CN25  0.01U_0402_16V7K  [C_0402]  261.07 23.32 270 top
CN26  0.01U_0402_16V7K  [C_0402]  260.18 23.32 270 top
CN29  0.01U_0402_16V7K  [C_0402]  259.43 15.4 270 top
CN30  0.01U_0402_16V7K  [C_0402]  262.02 23.32 270 top
CR1  4.7U_0603_6.3V6K  [C_0603]  292.2 29.06 90 top
CR2  0.1U_0402_25V6  [C_0402]  279.78 29.38 180 top
CR3  0.1U_0402_25V6  [C_0402]  291.08 29.3 90 top
CR4  0.1U_0402_25V6  [C_0402]  284.77 35.97 90 top
CR6  0.1U_0402_25V6  [C_0402]  287.13 25.11 270 top
CR7  4.7U_0603_6.3V6K  [C_0603]  280.72 24.5 90 top
CR8  0.1U_0402_25V6  [C_0402]  281.81 24.47 90 top
CR9  4.7U_0603_6.3V6K  [C_0603]  287.07 37.38 270 top
CR10  0.1U_0402_25V6  [C_0402]  285.66 36.89 270 top
CR13  0.1U_0402_25V6  [C_0402]  278.86 28.49 0 top
CR14  4.7U_0603_6.3V6K  [C_0603]  291.31 25.71 180 top
CR15  0.1U_0402_25V6  [C_0402]  290.83 26.78 180 top
CR17  1U_0402_6.3V6K  [C_0402]  278.86 27.55 0 top
CR18  4.7U_0603_6.3V6K  [C_0603]  290.81 35.39 180 top
CR19  0.1U_0402_25V6  [C_0402]  290.33 34.34 180 top
CR21  0.1U_0402_25V6  [C_0402]  280.38 35.01 270 top
CR22  0.1U_0402_25V6  [C_0402]  291.08 32.82 270 top
CR23  5P_0402_50V8C  [C_0402]  283.89 37.82 90 top
CR24  0.1U_0402_10V7K  [C_0402]  276.77 31.35 0 top
CR25  0.1U_0402_10V7K  [C_0402]  276.77 32.24 0 top
CR26  0.1U_0402_10V7K  [C_0402]  276.77 30.46 0 top
CR27  0.1U_0402_10V7K  [C_0402]  276.77 29.57 0 top
CR31  1U_0402_6.3V6K  [C_0402]  285.81 25.08 270 top
CR34  4.7U_0603_6.3V6K  [C_0603]  288.24 25.36 270 top
CR35  0.1U_0402_25V6  [C_0402]  274.51 27.08 270 top
CV1  0.1U_0402_10V7K  [C_0402]  113.93 94.78 270 bottom
CV2  0.1U_0402_10V7K  [C_0402]  114.82 94.78 270 bottom
CV3  0.1U_0402_10V7K  [C_0402]  115.71 94.78 270 bottom
CV4  0.1U_0402_10V7K  [C_0402]  116.6 94.78 270 bottom
CV5  0.1U_0402_10V7K  [C_0402]  117.49 94.78 270 bottom
CV6  0.1U_0402_10V7K  [C_0402]  118.38 94.78 270 bottom
CV9  10U_0603_6.3V6M  [C_0603]  105.33 90.47 0 top
CV10  0.01U_0402_16V7K  [C_0402]  99.59 92.62 90 top
CV11  1000P_0402_50V7K  [C_0402]  112.1 97.25 180 bottom
CV12  0.1U_0603_50V7K  [C_0603]  107.01 94.14 90 bottom
CV23  0.1U_0402_16V4Z  [C_0402]  223.21 91.54 180 bottom
CV26  0.1U_0402_10V7K  [C_0402]  219.92 94.54 270 bottom
CV27  10U_0603_6.3V6M  [C_0603]  221.05 94.88 270 bottom
CV60  2.2U_0402_6.3V6M  [C_0402]  229.73 75.47 270 bottom
CV61  0.01U_0402_16V7K  [C_0402]  223.8 84.35 270 top
CV62  0.01U_0402_16V7K  [C_0402]  221.64 85.68 180 bottom
CV66  0.1U_0402_25V6  [C_0402]  229.84 87.2 90 bottom
CV69  0.1U_0402_25V6  [C_0402]  221.71 75.48 270 bottom
CV71  0.1U_0402_25V6  [C_0402]  228.84 74.56 90 bottom
CV72  0.1U_0402_25V6  [C_0402]  227.95 74.56 90 bottom
CV73  0.1U_0402_25V6  [C_0402]  227.06 74.56 90 bottom
CV74  0.1U_0402_25V6  [C_0402]  226.17 74.56 90 bottom
CV75  0.1U_0402_25V6  [C_0402]  225.28 74.56 90 bottom
CV76  0.1U_0402_25V6  [C_0402]  224.39 74.56 90 bottom
CV77  0.1U_0402_25V6  [C_0402]  223.5 74.56 90 bottom
CV78  0.1U_0402_25V6  [C_0402]  222.61 74.56 90 bottom
CV79  0.1U_0402_25V6  [C_0402]  233.46 80.93 180 bottom
CV80  0.1U_0402_25V6  [C_0402]  233.46 81.82 180 bottom
CV145  0.1U_0402_25V6  [C_0402]  234.55 34.79 270 top
CV146  0.1U_0402_25V6  [C_0402]  233.66 34.79 270 top
CV147  0.1U_0402_25V6  [C_0402]  235.89 32 270 top
CV148  0.1U_0402_25V6  [C_0402]  235 32 270 top
CV149  0.1U_0402_25V6  [C_0402]  233.16 32.95 270 top
CV150  0.1U_0402_25V6  [C_0402]  232.27 32.95 270 top
CV152  0.1U_0402_25V6  [C_0402]  237.41 29.78 270 top
CV153  0.1U_0402_25V6  [C_0402]  236.52 29.78 270 top
CV156  0.1U_0402_25V6  [C_0402]  239.19 28.32 270 top
CV157  0.1U_0402_25V6  [C_0402]  238.3 28.32 270 top
CV501  0.1U_0402_10V7K  [C_0402]  287.33 74.9 180 bottom
CV502  0.1U_0402_10V7K  [C_0402]  287.33 74.01 180 bottom
CV503  0.1U_0402_10V7K  [C_0402]  288.68 73.13 180 top
CV504  0.1U_0402_10V7K  [C_0402]  288.68 72.24 180 top
CV505  0.1U_0402_10V7K  [C_0402]  288.68 74.9 180 top
CV506  0.1U_0402_10V7K  [C_0402]  288.68 74.02 180 top
CV507  0.1U_0402_10V7K  [C_0402]  288.68 76.68 180 top
CV508  0.1U_0402_10V7K  [C_0402]  288.68 75.79 180 top
CV509  .01U_0402_16V7K  [C_0402]  287.33 68.48 90 bottom
CV510  0.1U_0402_16V4Z  [C_0402]  283.98 64.87 180 bottom
CV512  0.1U_0402_10V7K  [C_0402]  277.76 69.89 180 bottom
CV513  0.1U_0402_10V7K  [C_0402]  277.76 70.78 180 bottom
CV514  0.1U_0402_25V6  [C_0402]  283.98 67.41 180 bottom
CZ1  0.1U_0402_25V6  [C_0402]  110.68 85.86 270 top
CZ2  0.1U_0402_16V4Z  [C_0402]  99.51 84.44 180 top
CZ4  0.1U_0402_25V6  [C_0402]  195.33 76.95 0 top
CZ5  4700P_0402_25V7K  [C_0402]  199.9 76.95 0 top
CZ6  2200P_0402_50V7K  [C_0402]  196.1 86.34 90 top
CZ7  2200P_0402_50V7K  [C_0402]  200.67 86.34 90 top
CZ9  0.1U_0402_25V6  [C_0402]  198.83 88.18 90 top
CZ13  0.1U_0402_10V7K  [C_0402]  229.52 24.94 0 top
CZ14  0.1U_0402_10V7K  [C_0402]  229.52 24.05 0 top
CZ15  0.1U_0402_25V6  [C_0402]  241.58 32.58 180 top
CZ16  0.047U_0402_16V4Z  [C_0402]  241.58 33.54 180 top
CZ17  0.1U_0402_25V6  [C_0402]  244.87 11.32 90 top
CZ18  0.1U_0402_25V6  [C_0402]  242.96 11.32 90 top
CZ19  4.7U_0603_6.3V6K  [C_0603]  241.83 31.47 180 top
CZ20  0.047U_0402_16V4Z  [C_0402]  243.91 12.24 270 top
CZ21  0.1U_0402_10V7K  [C_0402]  230.1 19.54 0 top
CZ22  0.1U_0402_10V7K  [C_0402]  230.1 18.65 0 top
CZ23  470P_0402_50V7K  [C_0402]  239.13 58.41 180 top
CZ25  220P_0402_50V7K  [C_0402]  162.51 86.12 270 top
CZ30  10P_0402_50V8J  [C_0402]  247.7 24.16 90 top
CZ31  10P_0402_50V8J  [C_0402]  246.81 24.16 90 top
CZ34  0.1U_0402_25V6  [C_0402]  268.91 34.55 0 top
CZ35  0.01U_0402_16V7K  [C_0402]  270.04 36.4 270 top
CZ36  0.1U_0402_10V7K  [C_0402]  245.12 29.15 180 top
CZ37  470P_0402_50V7K  [C_0402]  245.13 30.3 180 top
CZ38  10U_0603_6.3V6M  [C_0603]  161.44 83.58 90 top
CZ39  0.1U_0402_10V7K  [C_0402]  201.67 44.02 90 top
CZ40  0.1U_0402_10V7K  [C_0402]  223.4 62.82 90 top
CZ41  470P_0402_50V7K  [C_0402]  222.45 63.73 270 top
CZ42  470P_0402_50V7K  [C_0402]  239.13 57.53 180 top
CZ43  0.1U_0402_10V7K  [C_0402]  239.13 56.62 180 top
CZ44  0.1U_0402_10V7K  [C_0402]  218.49 39.3 270 top
CZ45  470P_0402_50V7K  [C_0402]  217.53 39.3 270 top
CZ46  1000P_0402_50V7K  [C_0402]  216.58 39.3 270 top
CZ47  0.1U_0402_10V7K  [C_0402]  215.68 36.88 0 top
CZ48  0.1U_0402_25V6  [C_0402]  263.84 55.67 180 top
CZ50  0.1U_0402_10V7K  [C_0402]  239.13 59.3 180 top
CZ64  470P_0402_50V7K  [C_0402]  221.5 63.73 270 top
DA1  AZ5123-02S.R7G_SOT23-3  [L03ESDL5V0CC3-2_SOT23-3]  16.89 17.42 270 top
DA2  -  [L03ESDL5V0CC3-2_SOT23-3]  16.94 15.13 180 bottom
DA3  AZ5123-02S.R7G_SOT23-3  [L03ESDL5V0CC3-2_SOT23-3]  19.03 13.44 90 top
DA4  -  [RB751S40T1G_SOD523-2]  25.1 13.7 0 top
DA5  -  [RB751S40T1G_SOD523-2]  25.1 15.04 0 top
DA6  -  [L03ESDL5V0CC3-2_SOT23-3]  3.81 7.51 180 bottom
DA7  -  [L03ESDL5V0CC3-2_SOT23-3]  7.81 7.51 180 bottom
DE1  -  [RB751S40T1G_SOD523-2]  64.08 87.03 225 top
DI1  -  [L05ESDL5V0NA-4_SLP2510P8-10-9]  86.03 92.69 180 bottom
DI2  -  [AZC199-02SPR7G_SOT23-3]  81.52 90.76 180 bottom
DI3  -  [AZC199-02SPR7G_SOT23-3]  243.38 92.53 0 bottom
DI4  -  [L05ESDL5V0NA-4_SLP2510P8-10-9]  285.45 60.52 90 bottom
DI5  -  [AZC199-02SPR7G_SOT23-3]  285 55.86 270 bottom
DI6  -  [L05ESDL5V0NA-4_SLP2510P8-10-9]  238.39 92.49 180 bottom
DV1  -  [BAT54CW_SOT323-3]  108.85 87.23 0 top
DV2  -  [BAT54CW_SOT323-3]  106.22 88.6 0 top
DV3  -  [BAT54CW_SOT323-3]  102.25 92.29 180 top
DV4  -  [AZC199-02SPR7G_SOT23-3]  98 94.44 180 bottom
DZ1  -  [RB751S40T1G_SOD523-2]  240.58 28.05 0 top
DZ2  -  [RB751S40T1G_SOD523-2]  240.58 29.19 0 top
DZ3  -  [RB751S40T1G_SOD523-2]  271.46 21.56 90 top
DZ4  -  [RB751S40T1G_SOD523-2]  271.46 25.3 270 top
FD1  FIDUCIAL MARK~D  [FIDUCIAL_C40M80]  23.24 7.85 0 top
FD2  FIDUCIAL MARK~D  [FIDUCIAL_C40M80]  276.32 76.96 0 top
FD3  FIDUCIAL MARK~D  [FIDUCIAL_C40M80]  10.32 12.55 180 bottom
FD4  FIDUCIAL MARK~D  [FIDUCIAL_C40M80]  271.93 73.88 180 bottom
H1  -  [H_2P3]  56.7 105.85 0 top
H2  -  [H_2P3]  118.7 105.85 0 top
H3  -  [H_2P3]  184.7 105.85 0 top
H4  -  [H_2P3]  230.2 105.85 0 top
H5  -  [H_5P5N]  258.95 98 0 top
H6  -  [H_2P3]  291.3 90.65 0 top
H7  -  [H_2P3]  69.98 61.55 0 top
H9  -  [H_2P3]  283.7 49.65 0 top
H10  -  [H_2P3]  240.35 43.65 0 top
H11  -  [H_2P3]  299.7 11.15 0 top
H12  -  [H_3P6]  236.8 8.1 0 top
H13  -  [H_2P3]  151.7 15.65 0 top
H14  -  [H_3P5]  122.5 74.58 0 top
H15  -  [H_3P5]  177.82 74.58 0 top
H16  -  [H_3P5]  122.5 52.43 0 top
H17  -  [H_3P5]  177.82 52.43 0 top
H18  -  [H_5P2X2P6N]  14.53 8.15 0 top
H19  -  [H_3P2]  266.87 24.6 0 top
H21  -  [H_2P3]  135.67 82 0 top
H22  -  [H_3P3]  92.2 88.9 0 top
H23  -  [H_2P6N]  294.32 11.15 0 top
JAPS1  ACES_50506-01841-P01  [ACES_50506-01841-P01_18P]  300.75 30.19 270 top
JDEG1  HB_A531015-SCHR21  [HB_A531015-SCHR21_10P]  298.14 40.63 270 top
JDIMM1  LCN_DAN06-K4406-0103  [LCN_DAN06-K4406-0103_204P]  79 16.43 180 bottom
JDIMM2  LCN_DAN06-K4406-0103  [LCN_DAN06-K4406-0103_204P-S]  160.5 16.43 180 bottom
JEDP1  ACES_50398-04041-001  [ACES_50398-04041-001_40P]  98.96 90.3 0 bottom
JFAN1  ACES_50271-0040N-001  [ACES_50271-0040N-001_4P]  62.04 87.97 138.2 bottom
JHDMI1  CONCR_099BKAC19YBLCNF  [CONCR_099BKAC19YBLCNF_19P-T]  210.7 100.07 0 bottom
JHP1  SINGA_2SJ3080-039111F  [SINGA_2SJ3080-039111F_6P-T]  11.55 15.25 270 bottom
JKBTP1  E-T_6705K-Y16N-00L  [E-T_6705K-Y16N-00L_16P]  244.5 23.1 270 top
JLED1  E-T_6705K-Y10N-00L  [E-T_6705K-Y10N-00L_10P-T]  266.15 11.13 0 top
JLOM1  SANTA_130456-511  [SANTA_130456-511_13P-T]  268.88 97.28 0 bottom
JLPDE1  HB_A531015-SCHR21  [HB_A531015-SCHR21_10P]  270.56 60.05 0 top
JMDP1  ACON_MAR2B-20K1803  [ACON_MAR2B-20K1803_20P-T]  293.95 77.55 270 bottom
JNGFF1  BELLW_80148-3221  [BELLW_80148-3221_67P-T]  233.34 33.85 270 bottom
JRTC1  TYCO_2-1775293-2~D  [TYCO_2-1775293-2_2P]  296.7 5.95 180 top
JSATA1  STARC_115B20-000000-G2-R  [STARC_115B20-000000-G2-R_20P-T]  258.94 6.75 0 bottom
JSD1  T-SOL_156-2000302608_NR  [T-SOL_156-2000302608_19P_NR-S]  271.72 36.87 270 bottom
JSPI1  E-T_6700K-Y20N-00L  [E-T_6700K-Y20N-00L_20P]  179.38 83.42 180 bottom
JSPK1  ACES_50279-0040N-001  [ACES_50279-0040N-001_4P]  4.21 12.2 0 top
JTAG1  @SHORT PADS~D  [SHORTPADS]  257.22 30.21 270 top
JUSB1  C-K_26210-8K1A-02  [C-K_26210-8K1A-02_9P-T]  88.2 95.87 0 bottom
JUSB2  C-K_26210-8K1A-02  [C-K_26210-8K1A-02_9P-T]  246.3 95.87 0 bottom
JUSB3  SINGA_2UB1641-000111F  [SINGA_2UB1641-000111F_9P-T]  288.8 52.65 270 bottom
JXDP1  SAMTE_BSH-030-01-L-D-A  [SAMTE_BSH-030-01-L-D-A_60P]  78.15 60.7 270 top
LA2  BLM15BD601SN1D_2P  [MURAT_BLM15BD601SN1D_2P]  21.74 13.63 270 top
LA3  BLM15BD601SN1D_2P  [MURAT_BLM15BD601SN1D_2P]  21.75 15.12 90 top
LA5  BLM15PX600SN1D_2P  [MURAT_BLM15PX600SN1D_2P]  26.21 20.58 90 top
LA6  BLM15PX330SN1D_2P  [MURAT_BLM15PX330SN1D_2P]  23.06 7.09 180 bottom
LA7  BLM15PX330SN1D_2P  [MURAT_BLM15PX330SN1D_2P]  23.06 8.55 180 bottom
LA8  BLM15PX330SN1D_2P  [MURAT_BLM15PX330SN1D_2P]  23.06 10.01 180 bottom
LA9  BLM15PX330SN1D_2P  [MURAT_BLM15PX330SN1D_2P]  23.06 11.48 180 bottom
LA10  BLM15PX330SN1D_2P  [MURAT_BLM15PX330SN1D_2P]  25.67 19.42 180 top
LA11  BLM15PX330SN1D_2P  [MURAT_BLM15PX330SN1D_2P]  24.15 17.58 180 top
LC1  2.2UH_LQM2MPN2R2NG0L_30%  [MURAT_LQM2MPN2R2NG0L_2P]  159.88 82.43 270 top
LC2  2.2UH_LQM2MPN2R2NG0L_30%  [MURAT_LQM2MPN2R2NG0L_2P]  162.21 82.43 270 top
LC3  2.2UH_LQM2MPN2R2NG0L_30%  [MURAT_LQM2MPN2R2NG0L_2P]  174.36 83.4 180 bottom
LC4  2.2UH_LQM2MPN2R2NG0L_30%  [MURAT_LQM2MPN2R2NG0L_2P]  159.62 82.11 90 bottom
LC5  2.2UH_LQM2MPN2R2NG0L_30%  [MURAT_LQM2MPN2R2NG0L_2P]  144.79 83.48 90 bottom
LED3  LTW-193ZDS5_WHITE  [LED_LTW-193ZDS5_2P]  295.45 87.55 0 top
LI1  DLW21HN900HQ2L_4P  [MURAT_DLW21HN900HQ2L_4P]  85.79 88.79 90 bottom
LI2  DLW21HN900HQ2L_4P  [MURAT_DLW21HN900HQ2L_4P]  87.44 88.79 90 bottom
LI3  DLW21HN900HQ2L_4P  [MURAT_DLW21HN900HQ2L_4P]  84.14 91.21 90 bottom
LI4  DLW21HN900HQ2L_4P  [MURAT_DLW21HN900HQ2L_4P]  242.84 86.63 90 bottom
LI5  DLW21HN900HQ2L_4P  [MURAT_DLW21HN900HQ2L_4P]  281.51 59.14 0 bottom
LI6  DLW21HN900HQ2L_4P  [MURAT_DLW21HN900HQ2L_4P]  281.51 60.8 0 bottom
LI7  DLW21HN900HQ2L_4P  [MURAT_DLW21HN900HQ2L_4P]  279.3 56.29 0 bottom
LI8  DLW21HN900HQ2L_4P  [MURAT_DLW21HN900HQ2L_4P]  239.78 88.54 90 bottom
LI9  DLW21HN900HQ2L_4P  [MURAT_DLW21HN900HQ2L_4P]  238.17 88.54 90 bottom
LL1  4.7UH_BRC2012T4R7MD_20%  [TAIYO_BRC2012T4R7MD_2P]  250.67 85.78 180 top
LV1  BLM15BB221SN1D_2P~D  [MURAT_BLM15BB221SN1D_2P]  109.21 88.31 0 top
LV3  DLW21HN900HQ2L_4P  [MURAT_DLW21HN900HQ2L_4P]  211.14 92.96 90 bottom
LV6  DLW21HN900HQ2L_4P  [MURAT_DLW21HN900HQ2L_4P]  217.43 92.96 90 bottom
LV10  DLW21HN900HQ2L_4P  [MURAT_DLW21HN900HQ2L_4P]  215.33 92.96 90 bottom
LV12  DLW21HN900HQ2L_4P  [MURAT_DLW21HN900HQ2L_4P]  213.24 92.96 90 bottom
LV27  DLW21HN900HQ2L_4P  [MURAT_DLW21HN900HQ2L_4P]  100.68 98.3 0 bottom
LZ1  DLW21HN900HQ2L_4P  [MURAT_DLW21HN900HQ2L_4P]  104.89 95.75 270 bottom
MIC1  SPM1437HM4H-6_6P  [KNOW_SPM1437HM4H-6_6P]  228.81 100.06 0 top
NOREF  -  []  230.2 105.85 0 top
NOREF#2  -  []  184.34 92.81 0 top
NOREF#3  -  []  69.98 61.55 0 top
NOREF#4  -  []  118.7 105.85 0 top
NOREF#5  -  []  240.35 43.65 0 top
NOREF#6  -  []  121.6 145.02 0 top
NOREF#7  -  []  122.5 52.43 0 top
NOREF#8  -  []  92.2 88.9 0 top
NOREF#9  -  []  177.82 52.43 0 top
NOREF#10  -  []  283.7 49.65 0 top
NOREF#11  -  []  291.3 90.65 0 top
NOREF#12  -  []  177.82 74.58 0 top
NOREF#13  -  []  122.5 74.58 0 top
NOREF#14  -  []  135.67 82 0 top
NOREF#15  -  []  299.7 11.15 0 top
NOREF#16  -  []  132.52 104.5 0 top
NOREF#17  -  []  56.7 105.85 0 top
NOREF#18  -  []  128.33 -47.65 0 top
NOREF#19  -  []  161.1 36.68 0 top
NOREF#20  -  []  266.87 24.6 0 top
NOREF#21  -  []  151.7 15.65 0 top
NOREF#22  -  []  236.8 8.1 0 top
NOREF#23  -  []  184.7 105.85 0 top
NOREF#24  -  []  179 97.64 0 top
NOREF#25  -  []  134.05 29.82 0 top
NOREF#26  -  []  203.63 38.66 180 bottom
NOREF#27  -  []  113.19 30.87 180 bottom
NOREF#28  -  []  199.89 91.25 180 bottom
NOREF#29  -  []  226.29 38.77 180 bottom
PBATT1  DEREN_40-42251-01001RHF  [DEREN_40-42251-01001RHF_10P-T]  60.7 16.55 180 bottom
PC1  1U_0603_10V4Z  [C_0603]  289.24 5.79 0 top
PC3  2200P_0402_50V7K  [C_0402]  63.24 12.38 0 top
PC9  1000P_0603_50V7K  [C_0603]  63.37 105.93 90 bottom
PC20  0.1U_0402_25V6  [C_0402]  66.37 103.69 0 top
PC21  10U_0805_25V6K  [C_0805]  61.73 100.89 90 top
PC22  10U_0805_25V6K  [C_0805]  64.91 105.77 90 bottom
PC100  4.7U_0603_10V6K  [C_0603]  218.3 48.37 270 bottom
PC101  10U_0805_25V6K  [C_0805]  218.23 57.86 270 bottom
PC102  10U_0805_25V6K  [C_0805]  218.23 57.86 270 top
PC105  2200P_0402_50V7K  [C_0402]  219.63 57.53 270 top
PC109  0.1U_0603_25V7K  [C_0603]  221.98 49.32 0 top
PC110  0.1U_0603_25V7K  [C_0603]  213.36 49.32 0 top
PC111  680P_0603_50V7K  [C_0603]  227.14 57.82 90 top
PC113  220U_6.3V_M  [C_APXK6R3ARA221MF451]  228.39 49.5 180 bottom
PC114  680P_0603_50V7K  [C_0603]  210.17 55.04 270 top
PC115  220U_6.3V_M  [C_APXK6R3ARA221MF451]  207.47 49.5 0 bottom
PC117  0.1U_0603_25V7K  [C_0603]  219.44 51.42 90 bottom
PC118  4.7U_0603_10V6K  [C_0603]  218.17 51.42 90 bottom
PC119  1U_0603_10V6K  [C_0603]  214.87 47.1 180 top
PC200  10U_0805_25V6K  [C_0805]  63.18 23.68 270 top
PC201  10U_0805_25V6K  [C_0805]  64.89 23.68 270 top
PC203  2200P_0402_50V7K  [C_0402]  62.1 22.85 270 bottom
PC204  0.22U_0603_16V7K  [C_0603]  65.97 15.66 270 bottom
PC205  22U_0805_6.3V6M  [C_0805]  70.63 12.11 0 bottom
PC207  220U_D2_2VY_R17M  [C_D2]  70.89 26.52 180 bottom
PC208  680P_0603_50V7K  [C_0603]  63.56 16.61 90 top
PC209  1U_0603_10V6K  [C_0603]  64.07 11.09 270 top
PC211  1U_0603_10V6K  [C_0603]  65.47 7.25 0 top
PC212  0.033U_0402_16V7K  [C_0402]  71.03 10.71 0 bottom
PC213  100P_0402_50V8J  [C_0402]  71.04 8.03 90 bottom
PC214  .1U_0402_16V7K  [C_0402]  71.03 9.82 0 bottom
PC215  .1U_0402_16V7K  [C_0402]  69 7.19 180 top
PC300  2200P_0402_50V7K  [C_0402]  199.07 62.15 270 bottom
PC301  680P_0603_50V7K  [C_0603]  201.72 58.66 180 top
PC302  0.1U_0603_25V7K  [C_0603]  204.64 62.59 180 top
PC303  10U_0805_25V6K  [C_0805]  200.39 62.68 270 bottom
PC304  330P_0402_50V7K  [C_0402]  207.69 59.54 90 bottom
PC305  47U_0805_6.3V6M  [C_0805]  204.21 50.73 0 top
PC306  47U_0805_6.3V6M  [C_0805]  204.21 52.45 0 top
PC307  22U_0805_6.3VAM  [C_0805]  201.08 50.72 180 top
PC308  22U_0805_6.3VAM  [C_0805]  201.08 52.43 180 top
PC309  4.7U_0603_6.3V6K  [C_0603]  206.68 62.59 0 bottom
PC310  4.7U_0603_6.3V6K  [C_0603]  204.33 63.93 0 bottom
PC400  1U_0402_6.3V6K  [C_0402]  115.6 74.02 0 bottom
PC401  4.7U_0805_6.3V6K  [C_0805]  113.74 76.88 180 bottom
PC402  .1U_0402_16V7K  [C_0402]  116.53 72.16 270 bottom
PC403  0.01U_0402_25V7K  [C_0402]  106.28 74.1 270 bottom
PC404  22U_0805_6.3V6M  [C_0805]  108.99 76.88 0 bottom
PC500  4700P_0603_50V7K  [C_0603]  104.63 63.1 270 bottom
PC501  .1U_0402_16V7K  [C_0402]  105.71 63.05 270 bottom
PC502  0.068U_0402_16V7K  [C_0402]  108.7 65.12 90 top
PC503  1000P_0402_50V7K  [C_0402]  97.44 55.73 0 bottom
PC504  0.1U_0402_25V6  [C_0402]  97.7 58.15 0 bottom
PC505  1U_0603_10V6K  [C_0603]  100.12 69.77 180 top
PC506  100P_0402_50V8J  [C_0402]  109.53 69.77 180 top
PC507  0.33U_0603_10V7K  [C_0603]  106.54 71.17 90 top
PC508  680P_0603_50V7K  [C_0603]  102.28 50.08 90 bottom
PC509  1U_0603_10V7K  [C_0603]  105.44 58.34 270 bottom
PC510  1U_0603_10V7K  [C_0603]  105.27 71.17 90 top
PC511  0.1U_0402_25V6  [C_0402]  98.85 72.75 270 top
PC512  1500P_0402_50V7K  [C_0402]  108.63 72.45 270 top
PC513  0.068U_0402_16V7K  [C_0402]  109.58 65.12 90 top
PC514  47P_0402_50V8J  [C_0402]  102.92 72.65 90 top
PC515  10U_0805_25V6K  [C_0805]  99.15 52.18 0 top
PC516  10U_0805_25V6K  [C_0805]  99.15 52.18 0 bottom
PC517  10U_0805_25V6K  [C_0805]  99.15 50.4 0 bottom
PC518  10U_0805_25V6K  [C_0805]  99.15 50.4 0 top
PC519  100U_D_20VM_R55M  [C_D]  97.14 46.91 0 bottom
PC520  2200P_0402_50V7K  [C_0402]  99.59 49.1 0 top
PC701  1U_0603_25V6K  [C_0603]  78.53 84.63 90 top
PC702  0.1U_0402_25V6  [C_0402]  78.67 87.55 180 bottom
PC703  0.1U_0402_25V6  [C_0402]  77.45 85.78 270 top
PC704  10U_0805_25V6K  [C_0805]  83.69 66.8 270 top
PC705  10U_0805_25V6K  [C_0805]  85.4 66.8 270 top
PC706  10U_0805_25V6K  [C_0805]  81.98 66.8 270 top
PC707  10U_0805_25V6K  [C_0805]  86.78 63.07 180 bottom
PC708  22U_0805_25V6M  [C_0805]  86.78 64.78 180 bottom
PC709  1U_0805_25V6K  [C_0805]  76.45 89.5 90 bottom
PC710  1U_0603_10V6K  [C_0603]  74.6 81.34 180 bottom
PC711  0.1U_0402_25V6  [C_0402]  79.61 85.78 270 top
PC712  0.047U_0603_25V7K~D  [C_0603]  73.2 83.87 0 bottom
PC713  2200P_0402_50V7K  [C_0402]  69.42 66.37 0 top
PC714  22U_0805_25V6M  [C_0805]  69.03 69.58 0 top
PC715  22U_0805_25V6M  [C_0805]  69.03 69.58 0 bottom
PC716  22U_0805_25V6M  [C_0805]  69.03 67.77 0 top
PC717  22U_0805_25V6M  [C_0805]  69.03 67.77 0 bottom
PC718  100P_0402_50V8J  [C_0402]  81.52 84.87 90 top
PC719  100P_0402_50V8J  [C_0402]  82.42 83.91 90 top
PC721  1000P_0603_50V7K  [C_0603]  74.06 78.29 270 top
PC722  0.1U_0603_25V7K  [C_0603]  90.59 64.03 270 top
PC723  10U_0805_25V6K  [C_0805]  88.96 64.17 270 top
PC724  10U_0805_25V6K  [C_0805]  88.71 64.13 270 bottom
PC725  10U_0805_25V6K  [C_0805]  90.59 64.13 270 bottom
PC726  0.1U_0402_25V6  [C_0402]  78.99 81.9 270 top
PC727  0.1U_0402_25V6  [C_0402]  78.98 80.11 0 top
PC728  0.1U_0402_25V6  [C_0402]  79.88 80.99 90 top
PC729  1U_0603_25V6K  [C_0603]  82.98 81.78 270 top
PC730  0.1U_0402_25V6  [C_0402]  72.55 97.54 0 top
PC731  0.022U_0603_50V7K  [C_0603]  67.62 98.82 270 top
PC734  10U_0805_25V6K  [C_0805]  67.38 92.95 180 bottom
PC900  22U_0805_6.3V6M  [C_0805]  119.29 57.8 90 bottom
PC901  22U_0805_6.3V6M  [C_0805]  123.61 64.29 90 bottom
PC902  22U_0805_6.3V6M  [C_0805]  122.21 67.39 90 bottom
PC903  22U_0805_6.3V6M  [C_0805]  122.21 57.8 90 bottom
PC904  22U_0805_6.3V6M  [C_0805]  123.61 60.92 90 bottom
PC913  22U_0805_6.3V6M  [C_0805]  120.81 60.92 90 bottom
PC914  22U_0805_6.3V6M  [C_0805]  118.02 60.92 90 bottom
PC915  2.2U_0805_10V6K  [C_0805]  119.42 67.39 90 bottom
PC916  2.2U_0805_10V6K  [C_0805]  120.81 64.29 90 bottom
PC917  22U_0805_6.3V6M  [C_0805]  118.02 64.29 90 bottom
PC966  220U 2.5V Y D2 ESR9M H1.9 SX  [C_D2]  115.19 57.19 180 bottom
PD1  -  [TVNST52302AB0_SOT523-3]  54.8 10.89 180 top
PD2  -  [TVNST52302AB0_SOT523-3]  52.7 10.89 180 top
PD3  -  [BAS40CW_SOT323-3]  288.74 7.86 270 top
PD5  -  [AZC199-02SPR7G_SOT23-3]  62.23 106.21 270 top
PD703  -  [PDS5100H-13_POWERDI5-3]  90.47 67.23 0 bottom
PD704  SDMK0340L-7-F_SOD323-2~D  [SDMK0340L-7-F_SOD323-2]  73.7 87.78 0 top
PD705  SDMK0340L-7-F_SOD323-2~D  [SDMK0340L-7-F_SOD323-2]  73.7 85.95 0 top
PH500  100K 1% 0402 B25/50 4250K  [R_0402]  100.49 58.97 0 bottom
PH501  10K +-1% 0402 B25/50 3370K  [R_0402]  109.24 51.88 90 top
PJP1  PAD-OPEN 1x3m  [JUMP_43X118]  62.66 92.73 0 bottom
PJP4  PAD-OPEN1x1m  [JUMP_43X39]  272.98 13.89 180 bottom
PJP5  PAD-OPEN1x1m  [JUMP_43X39]  273.36 11.67 180 bottom
PJP6  PAD-OPEN1x2m  [JUMP_43X79]  30.23 16.56 0 bottom
PJP7  PAD-OPEN1x1m  [JUMP_43X39]  256.32 21.35 0 top
PJP9  PAD-OPEN1X2m  [JUMP_43X79]  39.84 9.13 180 top
PJP10  PAD-OPEN1x1m  [JUMP_43X39]  44.14 10.2 180 top
PJP11  PAD-OPEN1x1m  [JUMP_43X39]  203.26 86.84 180 top
PJP12  PAD-OPEN1x1m  [JUMP_43X39]  246.36 26.85 90 top
